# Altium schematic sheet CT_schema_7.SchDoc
size 371 x 245 mm
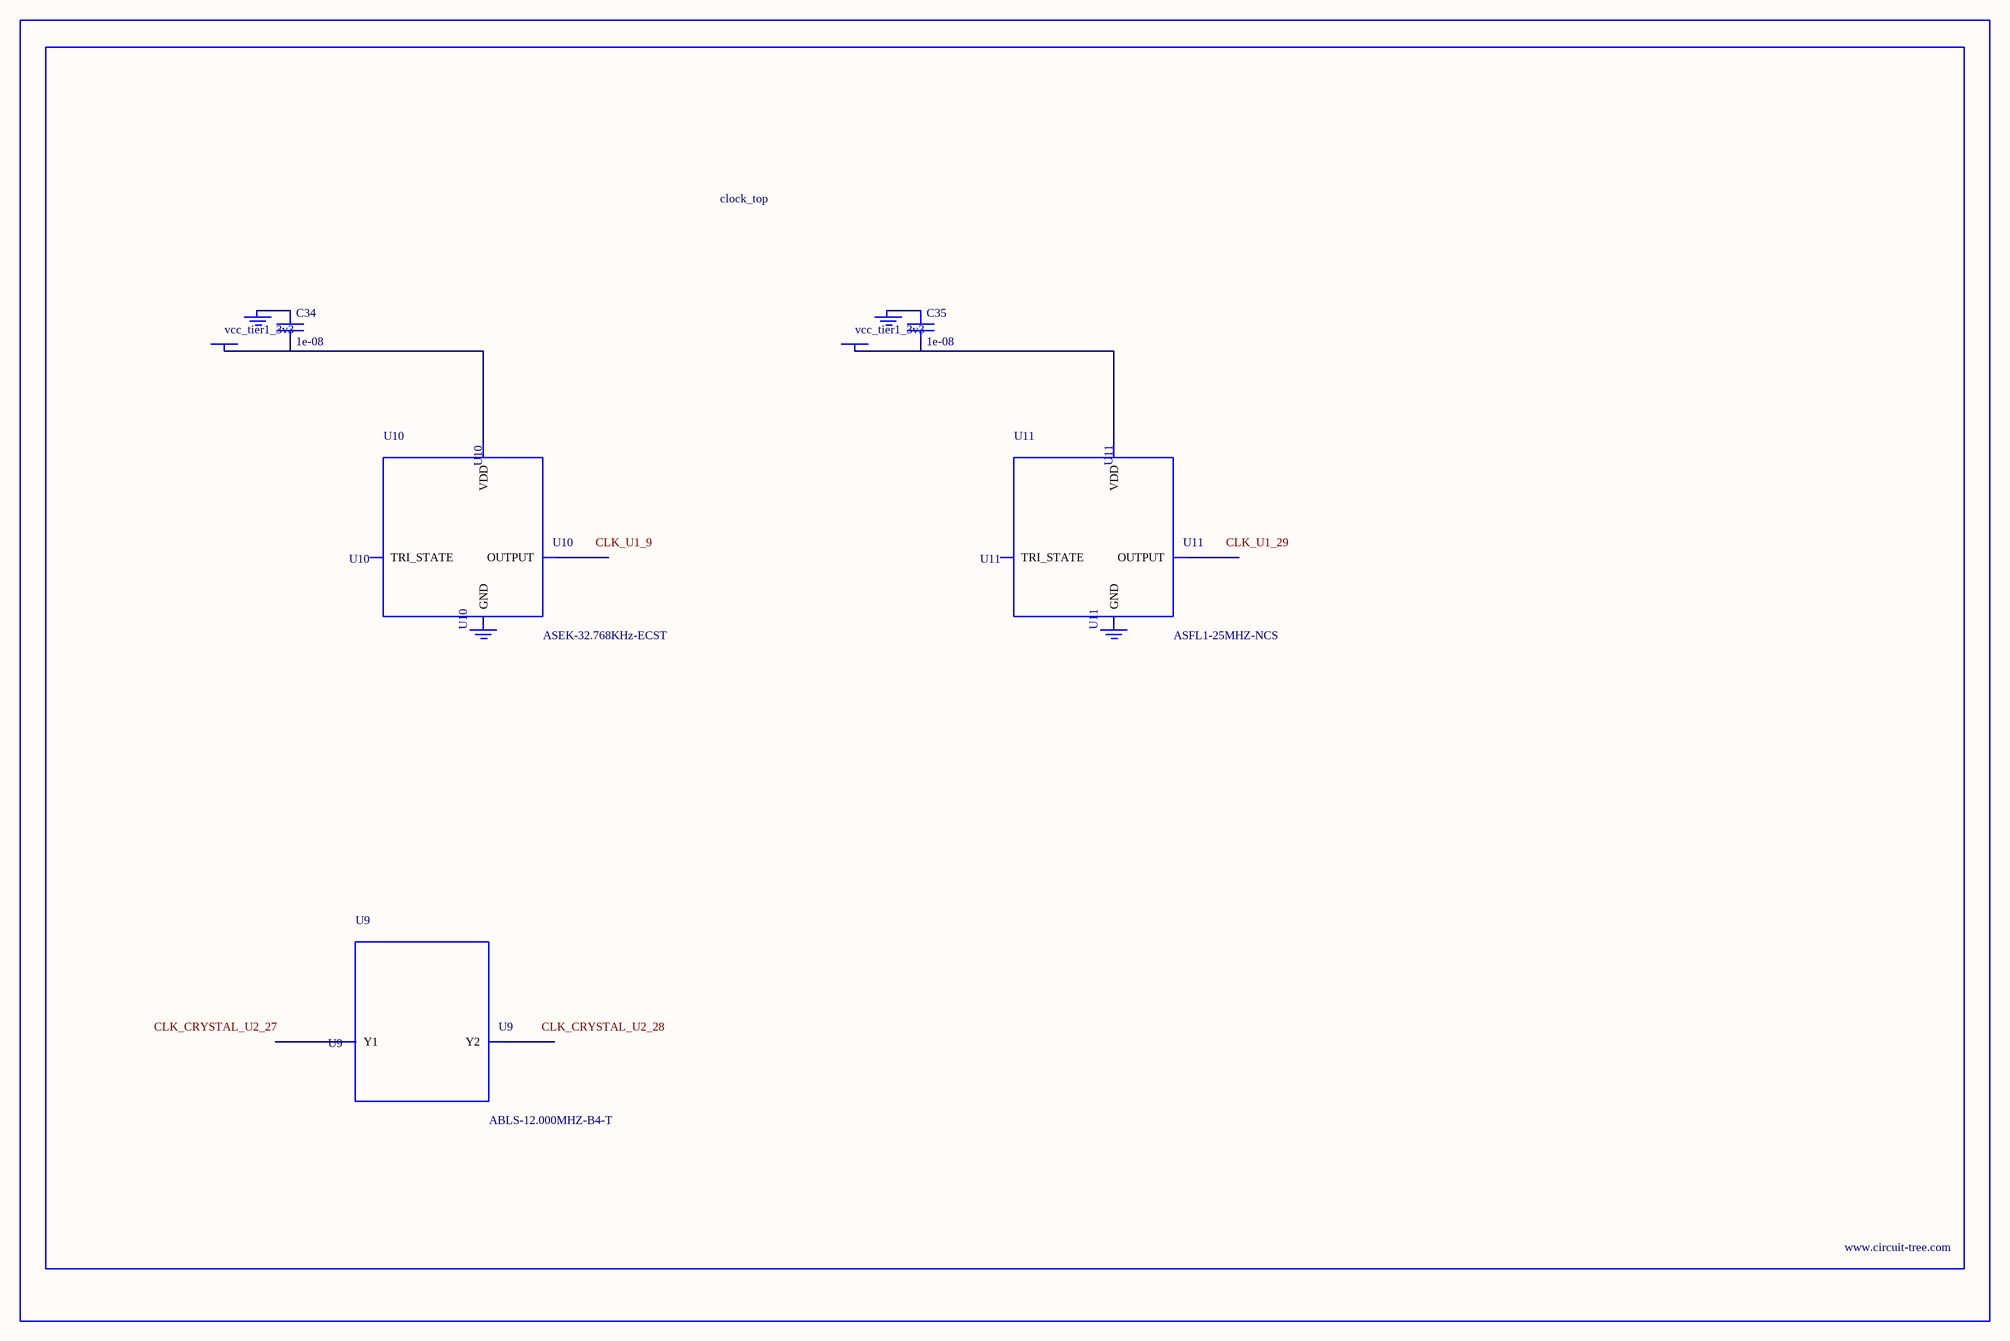
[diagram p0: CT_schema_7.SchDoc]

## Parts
BORDER6  (no value)
C34  1e-08  [C0402]
C35  1e-08  [C0402]
GND_INSTANCE_6_0  (no value)
GND_INSTANCE_6_1  (no value)
GND_INSTANCE_6_2  (no value)
GND_INSTANCE_6_3  (no value)
POWER_INSTANCE_6_0  vcc_tier1_3v3
POWER_INSTANCE_6_1  vcc_tier1_3v3
U9  ABLS-12.000MHZ-B4-T  [ABLS-12.000MHZ-B4-T]
U10  ASEK-32.768KHz-ECST  [ASEK]
U11  ASFL1-25MHZ-NCS  [ASFL1]

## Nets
NetC34_1: C34.1 GND_INSTANCE_6_0.0(GND)
NetC34_2: C34.2 POWER_INSTANCE_6_0.0(PWR) U10.4(VDD)
NetC35_1: C35.1 GND_INSTANCE_6_2.0(GND)
NetC35_2: C35.2 POWER_INSTANCE_6_1.0(PWR) U11.4(VDD)

Not connected (* = marked no-connect by the designer): GND_INSTANCE_6_1 0(GND); GND_INSTANCE_6_3 0(GND); U9 1(Y1) 2(Y2); U10 1(TRI_STATE) 2(GND) 3(OUTPUT); U11 1(TRI_STATE) 2(GND) 3(OUTPUT)

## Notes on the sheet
- Labels drawn without touching a wire or pin: CLK_CRYSTAL_U2_27, CLK_CRYSTAL_U2_28, CLK_U1_9, CLK_U1_29

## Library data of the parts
BORDER6 = BORDER_PAGE6
C34 C35 = C0402C103K3RAC
GND_INSTANCE_6_0-GND_INSTANCE_6_3 = GND
POWER_INSTANCE_6_0 POWER_INSTANCE_6_1 = PWR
